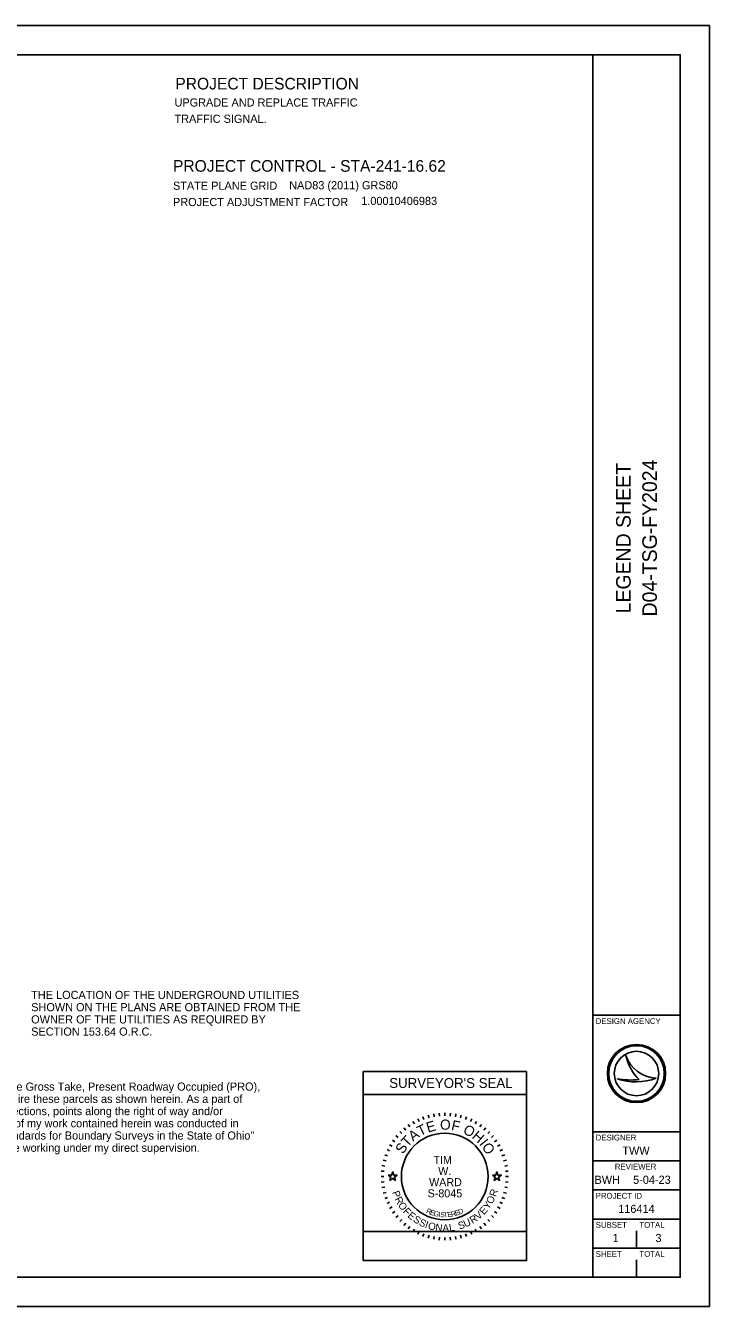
# Model space of a CAD drawing. Extents: x 0 to 34, y 0 to 22.
# Drawn here: x 22.27 to 34, y 0 to 22 of the extents above; entities that cross this region are included whole.
import ezdxf

# ---------------------------------------------------------------- set-up
doc = ezdxf.new("R2010")
doc.units = 0
for name, color, linetype in [('Default', 7, 'Continuous'), ('SH_Border', 7, 'Continuous'), ('SH_Cut_Line', 7, 'Continuous'), ('SH_Data', 7, 'Continuous'), ('SH_Text', 7, 'Continuous')]:
    doc.layers.add(name, color=color, linetype=linetype)

msp = doc.modelspace()

# ---------------------------------------------------------------- linework, layer by layer
at = {"layer": 'Default'}
for points in [[(28.49, 2.255), (28.549, 2.255), (28.567, 2.31), (28.585, 2.255), (28.643, 2.255), (28.596, 2.22), (28.614, 2.164), (28.567, 2.199), (28.519, 2.164), (28.537, 2.22)], [(30.277, 2.255), (30.336, 2.255), (30.354, 2.31), (30.372, 2.255), (30.431, 2.255), (30.384, 2.22), (30.402, 2.164), (30.354, 2.199), (30.307, 2.164), (30.325, 2.22)]]:
    msp.add_lwpolyline(points, close=True, dxfattribs=at)
at = {"layer": 'SH_Border'}
for p, q in [((32, 0.5), (32, 21.5)), ((32, 5), (33.5, 5)), ((32, 3), (33.5, 3)), ((32, 2.5), (33.5, 2.5)), ((32, 2), (33.5, 2)), ((32, 1.5), (33.5, 1.5)), ((32, 1), (33.5, 1))]:
    msp.add_line(p, q, dxfattribs=at)
msp.add_lwpolyline([(1.5, 21.5), (33.5, 21.5), (33.5, 0.5), (1.5, 0.5)], close=True, dxfattribs=at)
at = {"layer": 'SH_Cut_Line'}
msp.add_lwpolyline([(0, 0), (34, 0), (34, 22), (0, 22)], close=True, dxfattribs=at)
at = {"layer": 'SH_Data'}
for p, q in [((32.567, 4.31), (32.567, 4.31)), ((28.06, 0.787), (28.06, 4.037)), ((28.06, 4.037), (30.86, 4.037)), ((30.86, 4.037), (30.86, 0.787)), ((32.75, 4), (32.75, 4)), ((32.417, 3.91), (32.417, 3.91)), ((33.087, 3.919), (33.087, 3.919)), ((28.06, 3.637), (30.86, 3.637)), ((29.271, 3.307), (29.279, 3.257)), ((29.365, 3.319), (29.369, 3.269)), ((29.46, 3.323), (29.46, 3.273)), ((29.556, 3.319), (29.551, 3.269)), ((29.65, 3.307), (29.642, 3.257)), ((28.833, 3.126), (28.862, 3.085)), ((28.914, 3.177), (28.939, 3.133)), ((28.998, 3.221), (29.019, 3.176)), ((29.086, 3.257), (29.103, 3.21)), ((29.177, 3.286), (29.19, 3.238)), ((29.744, 3.286), (29.731, 3.238)), ((29.835, 3.257), (29.817, 3.21)), ((29.923, 3.221), (29.902, 3.176)), ((30.007, 3.177), (29.982, 3.133)), ((30.088, 3.126), (30.059, 3.085)), ((28.623, 2.933), (28.661, 2.9)), ((28.687, 3.003), (28.722, 2.968)), ((28.757, 3.067), (28.79, 3.029)), ((30.164, 3.067), (30.131, 3.029)), ((30.234, 3.003), (30.198, 2.968)), ((30.298, 2.933), (30.26, 2.9)), ((28.469, 2.692), (28.514, 2.671)), ((28.513, 2.776), (28.557, 2.751)), ((28.565, 2.857), (28.605, 2.828)), ((30.356, 2.857), (30.315, 2.828)), ((30.408, 2.776), (30.364, 2.751)), ((30.452, 2.692), (30.406, 2.671)), ((28.404, 2.513), (28.452, 2.5)), ((28.433, 2.604), (28.48, 2.587)), ((30.488, 2.604), (30.441, 2.587)), ((30.517, 2.513), (30.469, 2.5)), ((28.367, 2.23), (28.417, 2.23)), ((28.371, 2.325), (28.421, 2.321)), ((28.383, 2.42), (28.433, 2.411)), ((30.538, 2.42), (30.488, 2.411)), ((30.55, 2.325), (30.5, 2.321)), ((30.554, 2.23), (30.504, 2.23)), ((28.371, 2.134), (28.421, 2.139)), ((28.383, 2.04), (28.433, 2.048)), ((30.538, 2.04), (30.488, 2.048)), ((30.55, 2.134), (30.5, 2.139)), ((28.404, 1.947), (28.452, 1.959)), ((28.433, 1.855), (28.48, 1.873)), ((28.469, 1.767), (28.514, 1.788)), ((30.452, 1.767), (30.406, 1.788)), ((30.488, 1.855), (30.441, 1.873)), ((30.517, 1.947), (30.469, 1.959)), ((28.513, 1.683), (28.557, 1.708)), ((28.565, 1.602), (28.605, 1.631)), ((28.623, 1.527), (28.661, 1.559)), ((30.298, 1.527), (30.26, 1.559)), ((30.356, 1.602), (30.315, 1.631)), ((30.408, 1.683), (30.364, 1.708)), ((28.687, 1.456), (28.722, 1.492)), ((28.757, 1.392), (28.79, 1.43)), ((28.833, 1.334), (28.862, 1.375)), ((28.914, 1.282), (28.939, 1.326)), ((30.007, 1.282), (29.982, 1.326)), ((30.088, 1.334), (30.059, 1.375)), ((30.164, 1.392), (30.131, 1.43)), ((30.234, 1.456), (30.198, 1.492)), ((28.998, 1.238), (29.019, 1.284)), ((29.086, 1.202), (29.103, 1.249)), ((29.177, 1.173), (29.19, 1.221)), ((29.271, 1.152), (29.279, 1.202)), ((29.365, 1.14), (29.369, 1.19)), ((29.46, 1.136), (29.46, 1.186)), ((29.556, 1.14), (29.551, 1.19)), ((29.65, 1.152), (29.642, 1.202)), ((29.744, 1.173), (29.731, 1.221)), ((29.835, 1.202), (29.817, 1.249)), ((29.923, 1.238), (29.902, 1.284)), ((32.75, 1), (32.75, 1.3)), ((28.06, 0.787), (30.86, 0.787)), ((32.375, 0.675), (32.375, 0.675)), ((32.75, 0.5), (32.75, 0.8))]:
    msp.add_line(p, q, dxfattribs=at)
msp.add_lwpolyline([(28.06, 0.787), (28.06, 1.287), (30.86, 1.287), (30.86, 0.787)], close=True, dxfattribs=at)
for centre, radius in [((32.75, 4), 0.5), ((32.75, 4), 0.477), ((32.75, 4), 0.477), ((32.75, 4), 0.382), ((29.46, 2.23), 0.744)]:
    msp.add_circle(centre, radius, dxfattribs=at)
for centre, radius, start, end in [((33.116, 4.498), 0.58, 198.9257, 198.9319), ((33.347, 4.47), 0.796, 191.6379, 191.6421), ((33.116, 4.498), 0.58, 198.9319, 267.1657), ((33.347, 4.47), 0.796, 191.6421, 226.0947), ((32.739, 4.87), 1.013, 251.4576, 290.0832), ((32.648, 5.154), 1.266, 259.4964, 259.4995), ((32.739, 4.87), 1.013, 251.4527, 251.4576), ((32.648, 5.154), 1.266, 259.4995, 276.6672)]:
    msp.add_arc(centre, radius, start, end, dxfattribs=at)

# ---------------------------------------------------------------- texts
for s, height, rotation, p in [('D04-TSG-FY2024', 0.25, 90, (33.1, 11.851)), ('LEGEND SHEET', 0.25, 90, (32.65, 11.904)), ('T', 0.175, 25.7167, (29.037, 2.919)), ('E', 0.175, 15.7571, (29.171, 2.984)), ('O', 0.175, 359.7812, (29.379, 3.035)), ('F', 0.175, 347.4362, (29.562, 3.032)), ('O', 0.175, 332.2586, (29.76, 2.981)), ('T', 0.175, 46.4344, (28.821, 2.725)), ('A', 0.175, 36.4747, (28.915, 2.827)), ('H', 0.175, 319.9136, (29.914, 2.9)), ('I', 0.175, 308.367, (30.044, 2.79)), ('S', 0.175, 57.1924, (28.746, 2.606)), ('O', 0.175, 303.1491, (30.088, 2.741)), ('P', 0.125, 289.7431, (28.555, 1.96)), ('R', 0.125, 70.983, (30.337, 1.875)), ('R', 0.125, 296.9802, (28.597, 1.845)), ('O', 0.125, 304.7158, (28.652, 1.739)), ('Y', 0.125, 55.5058, (30.21, 1.655)), ('O', 0.125, 62.7428, (30.273, 1.746)), ('F', 0.125, 312.956, (28.734, 1.624)), ('E', 0.125, 319.6885, (28.811, 1.543)), ('S', 0.125, 326.9255, (28.905, 1.465)), ('R', 0.0875, 334.487, (29.132, 1.611)), ('E', 0.0875, 341.04, (29.199, 1.58)), ('G', 0.0875, 347.4752, (29.262, 1.557)), ('I', 0.0875, 353.7858, (29.347, 1.538)), ('S', 0.0875, 356.8926, (29.38, 1.533)), ('T', 0.0875, 3.0061, (29.443, 1.528)), ('E', 0.0875, 6.0117, (29.509, 1.531)), ('R', 0.0875, 11.9184, (29.576, 1.539)), ('E', 0.0875, 17.6836, (29.648, 1.555)), ('D', 0.0875, 23.3052, (29.712, 1.576)), ('R', 0.125, 33.296, (29.937, 1.414)), ('V', 0.125, 41.0316, (30.037, 1.481)), ('E', 0.125, 48.2687, (30.131, 1.564)), ('S', 0.125, 334.1626, (29.005, 1.401)), ('I', 0.125, 341.3997, (29.109, 1.352)), ('O', 0.125, 345.1351, (29.163, 1.332)), ('N', 0.125, 353.3752, (29.293, 1.299)), ('A', 0.125, 1.1108, (29.422, 1.285)), ('L', 0.125, 8.3479, (29.543, 1.288)), ('S', 0.125, 18.3234, (29.711, 1.318)), ('U', 0.125, 25.5604, (29.815, 1.353))]:
    msp.add_text(s, height=height, rotation=rotation, dxfattribs=at).set_placement(p)
for s, height, p in [('DESIGN AGENCY', 0.1, (32.05, 4.85)), ("SURVEYOR'S SEAL", 0.17, (28.508, 3.752)), ('DESIGNER', 0.1, (32.05, 2.85)), ('TWW', 0.14, (32.507, 2.605)), ('TIM ', 0.1375, (29.266, 2.448)), ('REVIEWER', 0.1, (32.378, 2.35)), ('WARD', 0.1375, (29.191, 2.065)), ('W.', 0.1375, (29.347, 2.257)), ('BWH', 0.14, (32.03, 2.105)), ('5-04-23', 0.14, (32.692, 2.105)), ('S-8045', 0.1375, (29.166, 1.873)), ('PROJECT ID', 0.1, (32.05, 1.85)), ('116414', 0.14, (32.436, 1.605)), ('SUBSET', 0.1, (32.05, 1.35)), ('TOTAL', 0.1, (32.8, 1.35)), ('1', 0.14, (32.339, 1.105)), ('3', 0.14, (33.075, 1.105)), ('SHEET', 0.1, (32.05, 0.85)), ('TOTAL', 0.1, (32.8, 0.85))]:
    msp.add_text(s, height=height, dxfattribs=at).set_placement(p)
at = {"layer": 'SH_Text'}
for s, height, p in [('PROJECT DESCRIPTION', 0.2, (24.838, 20.903)), ('UPGRADE AND REPLACE TRAFFIC', 0.14, (24.823, 20.61)), ('TRAFFIC SIGNAL.', 0.14, (24.823, 20.33)), ('PROJECT CONTROL - STA-241-16.62', 0.2, (24.797, 19.49)), ('STATE PLANE GRID', 0.14, (24.797, 19.18)), ('NAD83 (2011) GRS80           ', 0.14, (26.791, 19.188)), ('PROJECT ADJUSTMENT FACTOR', 0.14, (24.797, 18.9)), ('1.00010406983', 0.14, (28.027, 18.919)), ('THE LOCATION OF THE UNDERGROUND UTILITIES', 0.14, (22.364, 5.28)), ('SHOWN ON THE PLANS ARE OBTAINED FROM THE', 0.14, (22.364, 5.07)), ('OWNER OF THE UTILITIES AS REQUIRED BY', 0.14, (22.364, 4.86)), ('SECTION 153.64 O.R.C.', 0.14, (22.364, 4.65)), (', P. S.  have established the proposed property lines, calculated the Gross Take, Present Roadway Occupied (PRO),', 0.14, (16.616, 3.705)), ('Net Take and Net Residue; as well as prepared the legal descriptions necessary to acquire these parcels as shown herein. As a part of', 0.14, (14.82, 3.495)), ('this work I have set right of way monuments at the property corners, property line intersections, points along the right of way and/or', 0.14, (14.82, 3.285)), ('angle points on the right of way, Section Corners and other points as shown herein.  All of my work contained herein was conducted in', 0.14, (14.82, 3.075)), ('accordance with Ohio Administrative Code 4733-37 commonly known as "Minimum Standards for Boundary Surveys in the State of Ohio"', 0.14, (14.82, 2.865)), ('unless noted.  The words I and my as used herein are to mean either myself or someone working under my direct supervision.', 0.14, (14.82, 2.655))]:
    msp.add_text(s, height=height, dxfattribs=at).set_placement(p)

doc.saveas('drawing.dxf')
